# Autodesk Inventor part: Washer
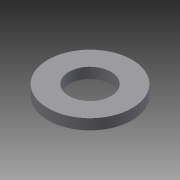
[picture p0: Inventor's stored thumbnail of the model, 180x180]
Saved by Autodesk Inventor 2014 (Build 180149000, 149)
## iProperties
Created: 2004-07
Part Number: Washer
Document SubType Name: Modeling
Designer: Autodesk, Inc.
Manufacturer: Standard
Standards Organization: Custom
Density: 1 g/cm^3
Mass: 2.41274 g
Surface Area: 18.0956 cm^2
Volume: 2.41274 cm^3
Material: Generic
Appearance: Default
Author: Autodesk, Inc.
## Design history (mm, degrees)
sketch "Sketch1"
  geometry: C1 r 16 at (0, 0); C2 r 8 at (0, 0)
  constraints: 2 centre point, 1 coincident
  dimensions: "d0" = 32 diameter of C1; "d1" = 16 diameter of C2
extrude "Extrusion1" new body sketch "Sketch1" distance "d2" = 4; taper "d3" = 0 deg
body "Solid1"
